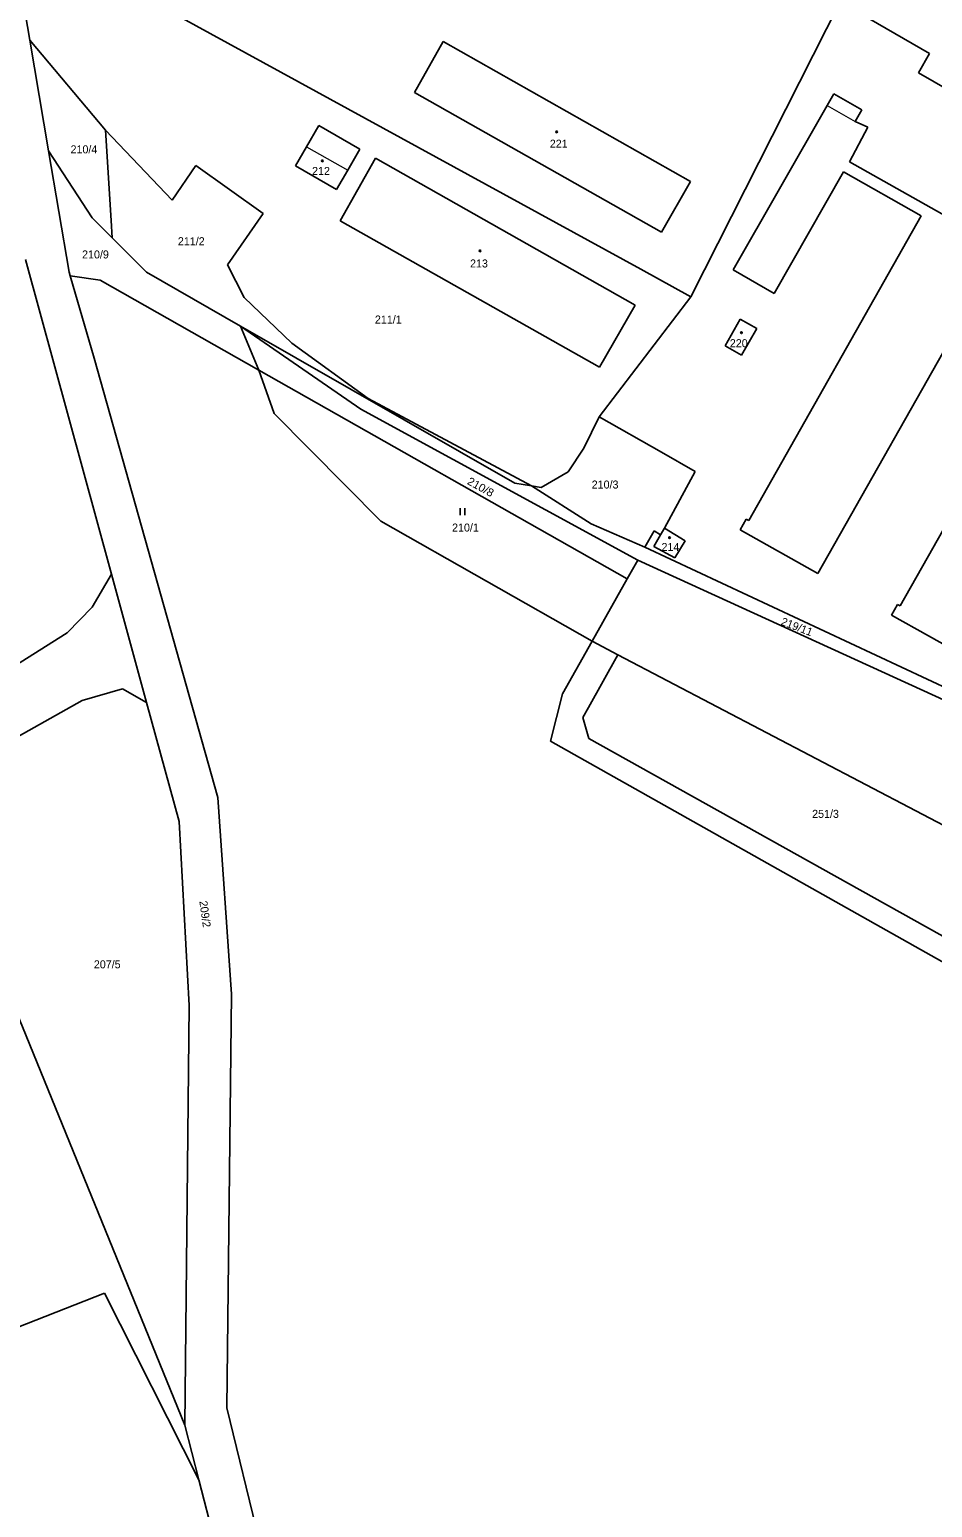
# Model space of a CAD drawing. Extents: x -633485 to -630509, y -1112692 to -1108818.
# Drawn here: x -631761.6 to -631569.8, y -1112246.7 to -1111932.7 of the extents above; entities that cross this region are included whole.
import ezdxf
from ezdxf.enums import TextEntityAlignment as Align

# ---------------------------------------------------------------- set-up
doc = ezdxf.new("R2010")
doc.units = 0
doc.header["$LTSCALE"] = 0.68
for name, color, linetype, lineweight in [('1', 7, 'Continuous', 25), ('3', 7, 'Continuous', 25), ('4', 7, 'Continuous', 13), ('5', 7, 'Continuous', 25)]:
    doc.layers.add(name, color=color, linetype=linetype, lineweight=lineweight)
doc.layers.add('2', color=7, linetype='Continuous')

msp = doc.modelspace()

# ---------------------------------------------------------------- linework, layer by layer
at = {"layer": '1'}
for p, q in [((-631747.56, -1111920.18), (-631631.76, -1111983.66)), ((-631763.67, -1111922.15), (-631761.5, -1111934.97)), ((-631621.1, -1111989.5), (-631589.4, -1111926.84)), ((-631585.18, -1111929.34), (-631570.43, -1111937.79)), ((-631761.5, -1111934.97), (-631757.54, -1111958.47)), ((-631761.5, -1111934.97), (-631745.45, -1111954.11)), ((-631679.8, -1111946.12), (-631673.75, -1111935.27)), ((-631673.75, -1111935.27), (-631621.21, -1111965.04)), ((-631572.8, -1111941.92), (-631570.43, -1111937.79)), ((-631572.8, -1111941.92), (-631561.19, -1111948.57)), ((-631679.8, -1111946.12), (-631627.34, -1111975.8)), ((-631592.19, -1111948.88), (-631590.78, -1111946.41)), ((-631590.78, -1111946.41), (-631584.83, -1111949.81)), ((-631612.13, -1111983.79), (-631592.19, -1111948.88)), ((-631586.24, -1111952.27), (-631584.83, -1111949.81)), ((-631700.17, -1111953.08), (-631691.41, -1111958.12)), ((-631587.45, -1111960.81), (-631583.54, -1111953.49)), ((-631586.24, -1111952.27), (-631583.54, -1111953.49)), ((-631745.45, -1111954.11), (-631731.3, -1111969.01)), ((-631745.45, -1111954.11), (-631744.25, -1111973.33)), ((-631757.54, -1111958.47), (-631748.27, -1111972.75)), ((-631757.54, -1111958.47), (-631753.19, -1111984.26)), ((-631694, -1111962.63), (-631691.41, -1111958.12)), ((-631731.3, -1111969.01), (-631726.27, -1111961.6)), ((-631726.27, -1111961.6), (-631711.96, -1111971.83)), ((-631705.08, -1111961.68), (-631696.36, -1111966.74)), ((-631696.36, -1111966.74), (-631694, -1111962.63)), ((-631695.63, -1111973.39), (-631688.09, -1111960.05)), ((-631688.09, -1111960.05), (-631632.97, -1111991.31)), ((-631587.45, -1111960.81), (-631490.99, -1112015.24)), ((-631627.34, -1111975.8), (-631621.21, -1111965.04)), ((-631603.4, -1111988.78), (-631588.69, -1111962.96)), ((-631588.69, -1111962.96), (-631572.19, -1111972.3)), ((-631719.51, -1111982.72), (-631711.96, -1111971.83)), ((-631608.81, -1112037.06), (-631572.19, -1111972.3)), ((-631748.27, -1111972.75), (-631744.02, -1111977)), ((-631744.25, -1111973.33), (-631744.02, -1111977)), ((-631695.63, -1111973.39), (-631640.52, -1112004.46)), ((-631744.02, -1111977), (-631736.73, -1111984.28)), ((-631762.44, -1111981.58), (-631744.2, -1112048.41)), ((-631594.15, -1112048.3), (-631556.24, -1111981.29)), ((-631753.19, -1111984.26), (-631752.96, -1111985.05)), ((-631736.73, -1111984.28), (-631716.77, -1111995.72)), ((-631719.51, -1111982.72), (-631716.03, -1111989.65)), ((-631631.76, -1111983.66), (-631621.1, -1111989.5)), ((-631612.13, -1111983.79), (-631603.4, -1111988.78)), ((-631752.96, -1111985.05), (-631746.62, -1111985.97)), ((-631752.96, -1111985.05), (-631747.83, -1112002.54)), ((-631746.62, -1111985.97), (-631712.87, -1112005.1)), ((-631716.03, -1111989.65), (-631705.88, -1111999.38)), ((-631640.58, -1112014.98), (-631621.1, -1111989.5)), ((-631576.65, -1112055.19), (-631540.08, -1111990.41)), ((-631640.52, -1112004.46), (-631632.97, -1111991.31)), ((-631613.84, -1111999.96), (-631610.63, -1111994.25)), ((-631610.63, -1111994.25), (-631607.11, -1111996.23)), ((-631716.77, -1111995.72), (-631712.87, -1112005.1)), ((-631716.77, -1111995.72), (-631658.48, -1112029.13)), ((-631716.77, -1111995.72), (-631691.2, -1112013.4)), ((-631610.33, -1112001.93), (-631607.11, -1111996.23)), ((-631705.88, -1111999.38), (-631689.64, -1112011.1)), ((-631613.84, -1111999.96), (-631610.33, -1112001.93)), ((-631747.83, -1112002.54), (-631721.62, -1112095.89)), ((-631712.87, -1112005.1), (-631634.62, -1112049.45)), ((-631712.87, -1112005.1), (-631709.66, -1112014.33)), ((-631689.64, -1112011.1), (-631654.99, -1112029.68)), ((-631709.66, -1112014.33), (-631686.99, -1112037.15)), ((-631691.2, -1112013.4), (-631632.39, -1112045.49)), ((-631643.88, -1112021.64), (-631640.58, -1112014.98)), ((-631640.58, -1112014.98), (-631627.33, -1112022.54)), ((-631647.2, -1112026.67), (-631643.88, -1112021.64)), ((-631627.33, -1112022.54), (-631620.21, -1112026.63)), ((-631652.92, -1112030), (-631647.2, -1112026.67)), ((-631626.72, -1112038.66), (-631620.21, -1112026.63)), ((-631658.48, -1112029.13), (-631654.99, -1112029.68)), ((-631654.99, -1112029.68), (-631642.3, -1112037.74)), ((-631654.99, -1112029.68), (-631652.92, -1112030)), ((-631686.99, -1112037.15), (-631642.07, -1112062.7)), ((-631642.3, -1112037.74), (-631630.86, -1112042.73)), ((-631610.65, -1112039.01), (-631609.37, -1112036.75)), ((-631609.37, -1112036.75), (-631608.81, -1112037.06)), ((-631630.86, -1112042.73), (-631628.93, -1112039.25)), ((-631628.99, -1112042.53), (-631627.54, -1112040.06)), ((-631628.93, -1112039.25), (-631627.54, -1112040.06)), ((-631627.54, -1112040.06), (-631626.72, -1112038.66)), ((-631626.72, -1112038.66), (-631622.3, -1112041.38)), ((-631624.52, -1112044.96), (-631622.3, -1112041.38)), ((-631610.65, -1112039.01), (-631594.15, -1112048.3)), ((-631630.86, -1112042.73), (-631565.45, -1112073.31)), ((-631628.99, -1112042.53), (-631624.52, -1112044.96)), ((-631634.62, -1112049.45), (-631632.39, -1112045.49)), ((-631632.39, -1112045.49), (-631566.68, -1112075.5)), ((-631748.28, -1112055.43), (-631744.2, -1112048.41)), ((-631744.2, -1112048.41), (-631736.75, -1112075.68)), ((-631642.07, -1112062.7), (-631634.62, -1112049.45)), ((-631753.62, -1112060.89), (-631748.28, -1112055.43)), ((-631578.48, -1112057.13), (-631577.2, -1112054.87)), ((-631577.2, -1112054.87), (-631576.65, -1112055.19)), ((-631578.48, -1112057.13), (-631561.99, -1112066.43)), ((-631764.9, -1112068.05), (-631753.62, -1112060.89)), ((-631648.36, -1112073.89), (-631642.07, -1112062.7)), ((-631642.07, -1112062.7), (-631636.61, -1112065.56)), ((-631642.87, -1112076.77), (-631636.61, -1112065.56)), ((-631636.61, -1112065.56), (-631539.54, -1112116.43)), ((-631750.38, -1112075.25), (-631741.82, -1112072.82)), ((-631741.82, -1112072.82), (-631736.75, -1112075.68)), ((-631785.86, -1112095.2), (-631750.38, -1112075.25)), ((-631736.75, -1112075.68), (-631729.84, -1112100.99)), ((-631650.96, -1112083.92), (-631648.36, -1112073.89)), ((-631644.04, -1112078.86), (-631642.87, -1112076.77)), ((-631644.04, -1112078.86), (-631642.76, -1112083.39)), ((-631650.96, -1112083.92), (-631548.3, -1112141.77)), ((-631642.76, -1112083.39), (-631551.47, -1112134.4)), ((-631721.62, -1112095.89), (-631718.69, -1112137.7)), ((-631729.84, -1112100.99), (-631727.69, -1112140.1)), ((-631766.84, -1112135.4), (-631728.62, -1112229.26)), ((-631719.65, -1112225.54), (-631718.69, -1112137.7)), ((-631728.62, -1112229.26), (-631727.69, -1112140.1)), ((-631798.01, -1112221.88), (-631745.69, -1112201.18)), ((-631745.69, -1112201.18), (-631725.61, -1112240.9)), ((-631719.65, -1112225.54), (-631698.79, -1112311.55)), ((-631728.62, -1112229.26), (-631725.61, -1112240.9)), ((-631725.61, -1112240.9), (-631713.72, -1112286.84))]:
    msp.add_line(p, q, dxfattribs=at)
msp.add_lwpolyline([(-631705.08, -1111961.68), (-631702.76, -1111957.62), (-631700.17, -1111953.08)], dxfattribs=at)
at = {"layer": '3'}
for p, q in [((-631670.141, -1112035.89), (-631670.141, -1112034.39)), ((-631669.14, -1112035.89), (-631669.14, -1112034.39))]:
    msp.add_line(p, q, dxfattribs=at)
at = {"layer": '4'}
for p, q in [((-631592.19, -1111948.88), (-631586.24, -1111952.27)), ((-631702.76, -1111957.62), (-631694, -1111962.63))]:
    msp.add_line(p, q, dxfattribs=at)
at = {"layer": '5'}
for centre in [(-631649.6168, -1111954.4692), (-631699.4068, -1111960.6292), (-631665.9168, -1111979.7492), (-631610.3768, -1111997.1392), (-631625.6468, -1112040.6792)]:
    msp.add_circle(centre, 0.175, dxfattribs=at)

# ---------------------------------------------------------------- texts
at = {"layer": '2'}
for s, p in [('221', (-631651.08, -1111957.825)), ('210/4', (-631752.88, -1111959.025)), ('211/2', (-631730.08, -1111978.545)), ('210/9', (-631750.43, -1111981.355)), ('213', (-631668.02, -1111983.275)), ('211/1', (-631688.23, -1111995.185)), ('220', (-631612.84, -1112000.215)), ('210/3', (-631642.18, -1112030.245)), ('210/1', (-631671.84, -1112039.385)), ('214', (-631627.35, -1112043.515)), ('251/3', (-631595.36, -1112100.215)), ('207/5', (-631747.93, -1112132.185))]:
    msp.add_text(s, height=1.7, dxfattribs=at).set_placement(p)
msp.add_text('212', height=1.7, dxfattribs=at).set_placement((-631699.679, -1111963.615), align=Align.CENTER)
at = {"layer": '2', "width": 1.05}
msp.add_text('210/8', height=1.7, rotation=331, dxfattribs=at).set_placement((-631668.786, -1112029.211))
at = {"layer": '2'}
for s, rotation, p in [('219/11', 339, (-631602.132, -1112059.156)), ('209/2', 278, (-631725.53, -1112117.959))]:
    msp.add_text(s, height=1.7, rotation=rotation, dxfattribs=at).set_placement(p)

doc.saveas('drawing.dxf')
